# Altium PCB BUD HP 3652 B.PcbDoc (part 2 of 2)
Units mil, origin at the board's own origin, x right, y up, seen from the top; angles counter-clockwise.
Board outline 2604 x 4002 mil, 2 copper layers (Top Layer, Bottom Layer); 80 components, 93 nets, 415 pads, 235 vias.
Unrouted connection lines stored in the file: 48.
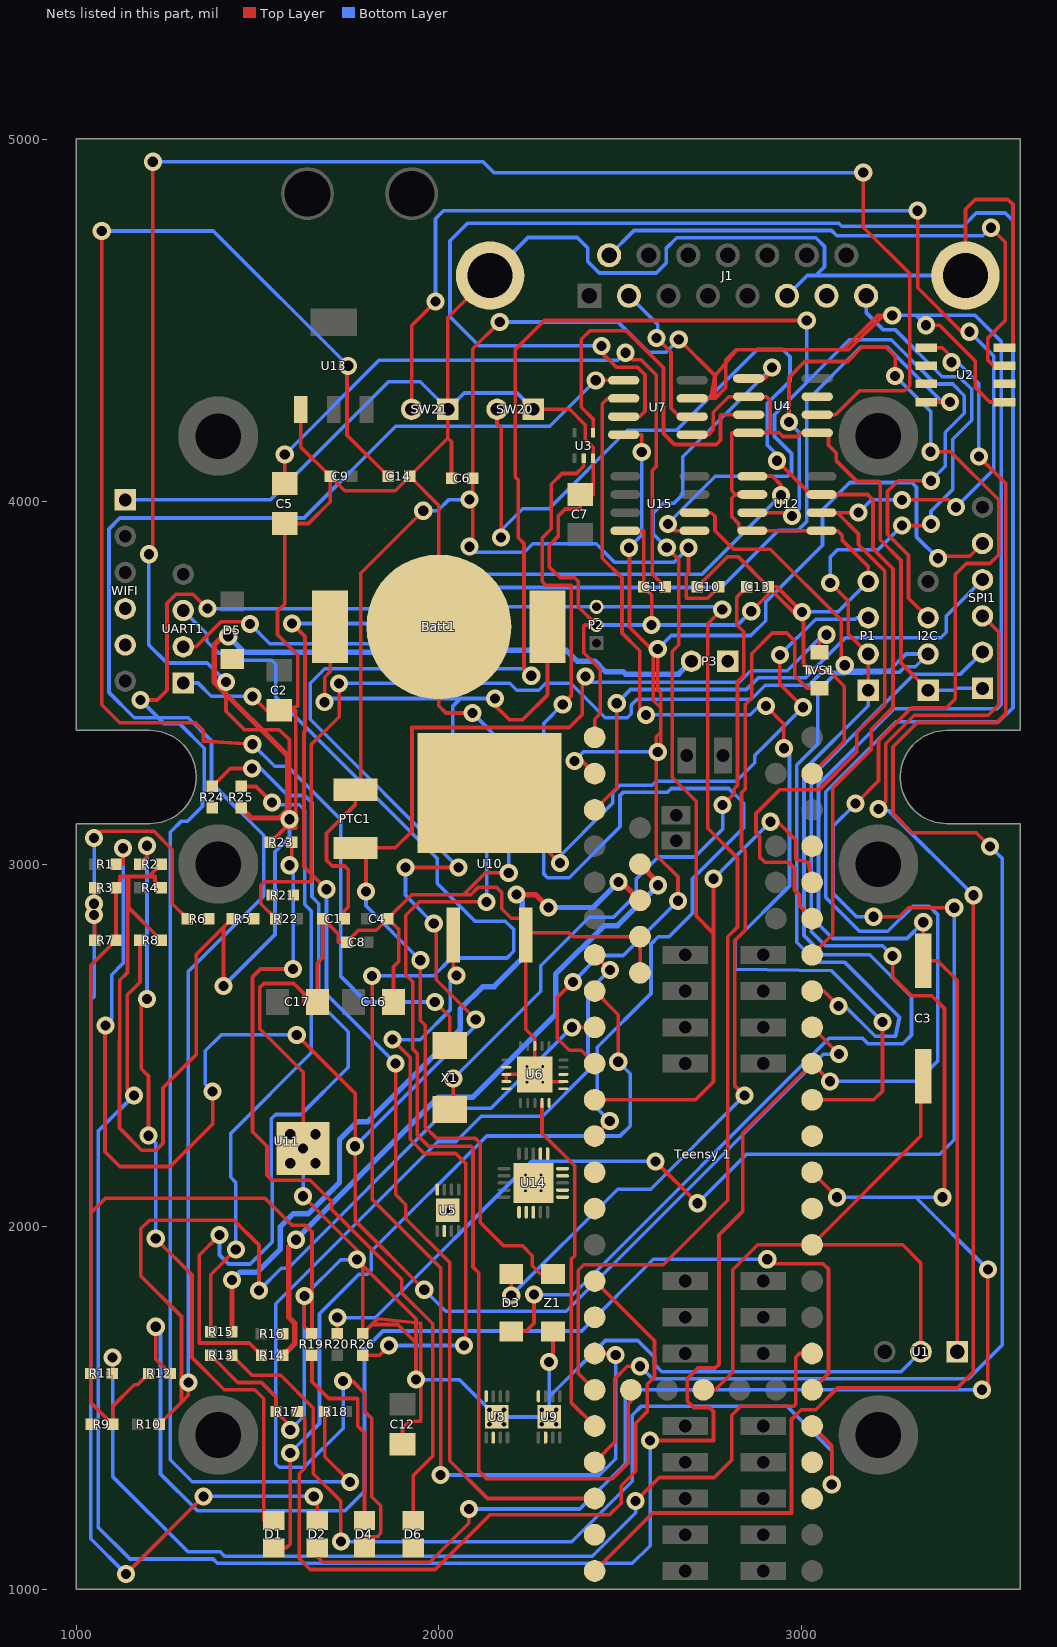
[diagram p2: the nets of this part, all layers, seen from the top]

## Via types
v1: diameter 50, hole 28, Top Layer to Bottom Layer, 215 vias
v2: diameter 20, hole 13, Top Layer to Bottom Layer, 12 vias
v3: diameter 19.68, hole 7.87, Top Layer to Bottom Layer, 8 vias

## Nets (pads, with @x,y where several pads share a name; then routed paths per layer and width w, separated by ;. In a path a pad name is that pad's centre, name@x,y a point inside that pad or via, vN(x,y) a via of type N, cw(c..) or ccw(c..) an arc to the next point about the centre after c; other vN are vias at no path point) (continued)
GND: "Teensy 1.14" "Teensy 1.17" "Teensy 1.32" "Teensy 1.78" "Teensy 1.79" "Teensy 1.90" Batt1.2 C1.1 C2.1 C3.2 C4.2 C5.1 C6.1 C7.2 C8.1 C9.1 C10.2 C11.1 C12.1 C13.1 C14.1 C16.1 C17.1 I2C.1 J1.6 J1.16 J1.17 P1.4 P2.2 R2.2 R3.2 R7.2 R8.2 R9.2 R11.2 R12.2 R13.2 R17.2 R19.2 R23.2 R26.2 SPI1.1 SW20.1 SW21.1 TVS1.3 U1.2 U2.8 U3.3 U4.2 U4.4 U4.5 U5.0 U5.2 U6.3 U6.4 U6.12 U6.18 U6.21 U7.5 U8.0 U8.2 U9.0 U9.2 U10.3 U11.29 U12.2 U12.4 U12.5 U13.1 U14.8 U14.21 U15.4 UART1.1 WIFI.1 Z1.1 | length 26122.3
  Top Layer w10: R12.2@1199.53,1595 1168.53,1564 1160,1564 1100,1504 R9.2@1100,1455 1040,1515 R11.2@1040,1595 1040,2037.9 ; R2.2@1234.05,3000 1200.05,2966 1144,2966 ; R8.2@1234.53,2790.06 1144,2880.59 1144,2966 ; R13.2@1370.47,1645 1445.47,1570 1510.95,1570 1550.95,1530 R17.2@1550.95,1490 1590,1450.95 v1(1590,1439) ; v1(1486,3463) 1524.12,3424.88 C2.1@1560,3424.88 ; R23.2@1535.47,3060 1575.51,3100.04 1605,3100.04 1605,3424.88 C2.1@1560,3424.88 ; U13.1@1619.45,4255 1619.45,4151.03 C9.1@1700.47,4070 ; v1(1625.71,2083.88) 1790,1919.58 v1@1790,1893 ; U11.29@1625.71,2215.91 1625.71,2426.29 1506,2546 1506,2660 1517,2671 1600,2671 1628,2643 1628,2620 C17.1@1665.12,2620 1665.12,2727 1680,2741.88 C1.1@1680,2850 1723,2807 1723,2785 C8.1@1745.47,2785 1778.47,2818 1827.53,2818 C4.2@1859.53,2850 ; v1(1629,1808.85) 1629,1725.53 R19.2@1650,1704.53 1650,1986 1632,2004 1595.08,2004 1521.18,2077.9 1080,2077.9 1040,2037.9 ; v1(1774,1909) v1@1790,1893 ; C16.1@1875,2620 1875,2717 1889,2731 1889,2820.53 C4.2@1859.53,2850 ; C12.1@1900,1399.88 1900,1443.62 1920,1463.62 1950.44,1463.62 1950.44,1733.35 1937,1734.82 ; v1(1937,1578) 1937,1680 ; C6.1@2035,4065 2035,4165.47 2025,4175.47 ; v1(2093,3417) 2020,3417 2000,3437 Batt1.2@2000,3655 2000,3989.53 C14.1@1919.53,4070 ; J1.16@2141.26,4624.09 2025,4507.83 SW21.1@2025,4255 2025,4175.47 ; U6.4@2186.26,2400.32 U6.3@2186.26,2420 U6.21@2265,2420 ; v1(2193,2976) 2128,2976 2068,2916 ; SW20.1@2260.71,4255 2361,4255 2404,4212 2404,4171.59 2425.59,4150 U3.3@2425.59,4119.57 2425.59,4020 C7.2@2390,4020 ; v1(2304.37,1626.37) 2315,1637 Z1.1@2315,1711 ; U6.12@2343.74,2400.32 2284.68,2400.32 U6.21@2265,2420 ; C7.2@2390,4020.12 C7.2@2390,4020 ; 2430,3350 2430,3400 2445,3415 2445,3538.33 2400,3583.33 2400,3657 2403,3660 P2.2@2435,3660 2385,3710 2385,3780 2375,3790 2335,3790 2305,3820 2305,3880.19 2330,3905.19 2330,3961 2349,3980 2390,3980 C7.2@2390,4020 ; U15.4@2514.53,3920 2565,3920 2565.47,3919.53 C11.1@2565.47,3765 2587,3743.47 v1(2587,3660) ; 2555,2700 2555.85,2700.85 2555.85,2765 2555,2765.85 2555,2800 2369.78,2800 2359.41,2810.37 U10.3@2240,2810.37 ; U7.5@2698.98,4185 2744,4185 2757.28,4198.28 2757.28,4247.28 2800,4290 U4.2@2855,4290 2904,4290 2914,4280 2914,4200 2904,4190 ; C10.2@2713.11,3765 2796.86,3848.75 2825.31,3848.75 C13.1@2909.05,3765 ; 2730,1550 2762.34,1550 2811,1598.66 2811,1881 2880,1950 3030,1950 ; v1(2862,3698) 2909.05,3745.05 C13.1@2909.05,3765 ; U12.2@2865,4020 2818,4020 ; v1(3002,3696) 2933,3765 C13.1@2909.05,3765 ; 3030,3250 3118.65,3338.65 3118.65,3491.35 TVS1.3@3075,3535 TVS1.3@3025,3535 3006,3554 3006,3668.05 C13.1@2909.05,3765 ; P1.4@3185,3780 3185,3821.58 3113.54,3893.04 3113.54,3906.46 3100,3920 U12.5@3055.94,3920 U12.4@2865,3920 2827.08,3920 2827.08,3940 2808,3959.08 2808,4010 2818,4020 ; U1.2@3330,1655 3330,1900 3280,1950 3030,1950 ; C3.2@3336.5,2415 3336.5,2344.93 3330,2344.93 3330,2250 3030,1950 ; I2C.1@3350,3480 3275,3555 3275,3837.74 3218,3894.74 3218,4051 3213,4056 3154,4056 3096,4114 3096,4135 3075,4156 3075,4190 U4.5@3043.98,4190 2999,4190 2989,4180 2949,4180 2939,4190 2904,4190 ; J1.17@3453.07,4624.09 3453.07,4807.07 3480,4834 3570,4834 3584,4820 3584,4425 U2.8@3560.75,4425 ; 1040,2037.9 1040,2720.54 R7.2@1109.53,2790.06 R3.2@1109.53,2935 1120.53,2946 1120.53,2966 1144,2966 ; C2.1@1560,3424.88 1611,3435.88 1611,3577 1555,3633 1555,3698 1575,3718 C5.1@1575,3939.88 1640.36,3939.88 1700.47,4000 C9.1@1700.47,4070 ; C9.1@1700.47,4070 1740.48,4030 1879.52,4030 C14.1@1919.53,4070 ; v1@1790,1893 1937,1746 1937,1734.82 ; v1@1790,1893 R26.2@1790,1704.53 1815.47,1730 ; 1815.47,1730 1831.84,1746.37 1937,1734.82 ; 1815.47,1730 1887,1730 1937,1680 ; C4.2@1859.53,2850 1925.53,2916 2068,2916 ; C14.1@1919.53,4070 2025,4175.47 ; 1937,1680 1937,1734.82 ; 2068,2916 2088,2916 2108,2936 2160,2936 2174,2922 2174,2877 2200,2851 2240,2851 U10.3@2240,2810.37 ; U10.3@2240,2810.37 U10.3@2240,2804.84 2240,2545 2265,2520 U6.18@2265,2498.74 U6.21@2265,2420 ; 2818,4020 2808,4030 2808,4190 U4.4@2855,4190 2904,4190
  Bottom Layer w10: WIFI.1@1135,4005 1535,4005 1861.09,4331.09 1948.91,4331.09 SW21.1@2025,4255 2070,4300 2215.71,4300 SW20.1@2260.71,4255 ; UART1.1@1295,3500 1335.51,3500 1372.51,3463 v1(1486,3463) ; v1(1590,1439) 1629,1478 v1(1629,1808.85) 1729.15,1909 v1(1774,1909) ; v1(1625.71,2083.88) U11.29@1625.71,2215.91 ; v1(1937,1578) 2057,1578 v2(2140,1495) U8.0@2160,1475 U9.0@2304.37,1475 2304.37,1530.37 ; v1(2093,3417) 2193,3317 v1(2193,2976) ; J1.16@2141.26,4624.09 2246.17,4729 2382,4729 2411,4700 2411,4663 2443,4631 2600,4631 2628,4659 2628,4700 2656.27,4728.27 3040,4728.27 3064,4704.27 3064,4648 3040.09,4624.09 ; v1(2304.37,1626.37) 2304.37,1530.37 ; P2.2@2435,3660 v1(2587,3660) 2824,3660 v1(2862,3698) ; J1.6@2960.75,4568.19 3016.56,4624 ; v1(3002,3696) 3101,3696 P1.4@3185,3780 ; U1.2@3330,1655 3275,1600 2615,1600 2595,1620 2595,1640 2549,1686 2460,1686 2304.37,1530.37 ; I2C.1@3350,3480 3422,3480 3427,3485 SPI1.1@3500,3485 ; J1.17@3453.07,4624.09 3040.09,4624.09 ; 3016.56,4624 3016.65,4624.09 3040.09,4624.09 ; 3016.56,4624 3040,4624 3040.09,4624.09
  other v2: 2140,1455 2180,1455 2284.37,1455 2324.37,1455 2180,1495 2284.37,1495 2324.37,1495
  other v3: 2239.05,2098.98 2282.36,2098.98 2239.05,2142.28 2282.36,2142.28 2243.35,2398.35 2286.65,2398.35 2243.35,2441.65 2286.65,2441.65
"GPS RX": "Teensy 1.41" P2.3 UART1.2 | length 4118.3
  Top Layer w10: UART1.2@1295,3600 1330.2,3600 1399.2,3669 1473,3669 v1(1479,3663) ; 2430,1550 2385,1595 2385,1880 2400,1895 2619,1895 2797,2073 2797,2800 2824,2827 2824,3017 2742,3099 2742,3663 v1(2782,3703)
  Bottom Layer w10: v1(1479,3663) 1534,3608 2053,3608 2155,3710 P2.3@2435,3710 2775,3710 v1(2782,3703)
"GPS TX": "Teensy 1.40" UART1.3 | length 4162
  Top Layer w10: v1(1816,2692) 1816,2075 2005,1886 v1(2005,1315) ; 2430,1650 2484,1650 v1(2488,1646)
  Bottom Layer w10: UART1.3@1295,3700 1359.53,3635.47 1359.53,3615.47 1393.51,3581.49 1413.68,3581.49 1432.67,3562.5 1538.79,3562.5 1550.14,3551.14 1550.14,3461.56 1996,3015.71 1996,2947 2100,2843 2183.53,2843 2206.53,2820 2206.53,2759.53 2188.06,2741.06 2035.06,2741.06 1986,2692 v1(1816,2692) ; v1(2005,1315) 2443,1315 2488,1360 v1(2488,1646)
"Hst USB_N": "Teensy 1.76" R14.1 | length 1895.3
  Top Layer w15: R14.1@1570,1645 1603,1678 1603,1733.5 1586.5,1750 1586.5,1944.5 v1(1606,1964) ; 2555,3000 2605,2950 v1(2605,2941.82)
  Bottom Layer w15: v1(1606,1964) 1999.49,2357.49 2094.07,2357.49 2322.5,2585.92 2322.5,2696.5 2456.48,2830.48 2493.66,2830.48 v1(2605,2941.82)
"Hst USB_P": "Teensy 1.77" R15.1 | length 2037.6
  Top Layer w15: R15.1@1429.53,1710 v1(1429.53,1852.53) ; v1(2214,2916) 2267,2916 v1(2302.5,2880.5) ; v1(2496,2951) 2504,2951 2555,2900
  Bottom Layer w15: v1(1429.53,1852.53) 1451.5,1874.5 1499.5,1874.5 1563,1938 1563,2000 1599,2036 1640,2036 1726,2122 1726,2240 1775.47,2289.47 1804.65,2289.47 2059,2543.82 2059,2600 2121.5,2662.5 2152.5,2662.5 2230,2740 2230,2900 v1(2214,2916) ; v1(2302.5,2880.5) 2425.5,2880.5 v1(2496,2951)
"J1708 RX": "Teensy 1.4" "Teensy 1.29" U4.1 | length 3246.2
  Top Layer w10: 2430,2350 2708,2350 2758,2400 2758,2809 ; v1(2629,3874) 2662.36,3840.64 2662.36,3605.36 2644,3587 2644,3240 2710,3174 2710,2857 2758,2809 ; v1(2758,2960) 2758,2809 ; U4.1@2855,4340 2899,4340 2919,4360 v1(2919,4370) ; v1(2915,3117) 2935,3117 2985,3067 2985,3014 3020,3005 3030,2950
  Bottom Layer w10: v1(2629,3874) 2592,3911 2592,3968 2620,3996 2649,3996 2673,4020 2673,4124 v1(2919,4370) ; v1(2758,2960) v1(2915,3117)
"J1708 TX": "Teensy 1.3" U3.2 | length 3181.5
  Top Layer w10: v1(2342,3441) 2365,3464 2365,3770 2295,3770 2285,3780 2285,3900.19 2310,3925.19 2310,4048 2340,4078 2380,4078 2400,4098 U3.2@2400,4119.57 ; 2430,2250 v1(2471.5,2291.5)
  Bottom Layer w10: v1(2342,3441) 2290,3389 2290,2973 2300,2963 2360,2963 2500,3103 2500,3189.71 2508.29,3198 2630.63,3198 2641.63,3209 2800,3209 2841,3168 2841,3101 2700,2960 2700,2865 2635,2800 2605.49,2800 2585.49,2780 2585.49,2643.21 2437.28,2495 2437.28,2325.72 v1(2471.5,2291.5)
J1708+: R5.2 U6.5
J1708-: R6.2 U6.2
LIN: J1.2 U6.10 U7.6 | length 428.9
  Top Layer w10: v1(2600.67,4452.05) 2640.67,4412.05 2640.67,4258 2663.67,4235 U7.6@2698.98,4235
  Bottom Layer w10: J1.2@2524.53,4568.19 2603.98,4488.74 2603.98,4455.36 v1(2600.67,4452.05)
"LIN1 RX": "Teensy 1.6" R10.1 U7.1 | length 6683.4
  Top Layer w10: R10.1@1229.05,1455 1290,1515.95 ; v1(1309,1570) 1309,1534.95 1290,1515.95 ; v1(1504,1824) 1504,1949.22 1436,2017.22 1201.22,2017.22 1178,1994 1178,1864 1290,1752 1290,1515.95 ; v1(2367.2,2550) 2430,2550 ; v1(2433,4335) U7.1@2510,4335
  Bottom Layer w10: v1(1309,1570) 1309,2704 1517,2912 1517,3080 1373,3224 1373,3340 1309,3404 1160,3404 1090,3474 1090,3925 1120,3955 1628,3955 1881,4208 2306,4208 v1(2433,4335) ; v1(1504,1824) 1565.5,1885.5 1584.5,1885.5 2026.17,2327.17 2144.37,2327.17 v1(2367.2,2550)
"LIN1 TX": "Teensy 1.5" U7.4 | length 2103.9
  Top Layer w10: v1(2370,2675) 2327,2632 2327,2520 2360,2487 2393,2487 2430,2450 ; U7.4@2510,4185 2560,4185 v1(2560,4137) ; v1(2525,3873) 2526,3872 2526,3654 2592,3588 2592,3452 2612,3432 2612,3364 2600,3352 2600,3025 2660,2965 v1(2660,2899)
  Bottom Layer w10: v1(2370,2675) 2443,2748 2509,2748 v1(2660,2899) ; v1(2525,3873) 2560,3908 v1(2560,4137)
"LIN !WAKE": "Teensy 1.24" R8.1 U7.3 | length 11016.5
  Top Layer w10: v1(1159,2362) 1140,2381 1140,2638.72 1175.47,2674.2 R8.1@1175.47,2790.06 ; v1(2449,4430) 2449,4412 2490,4371 2548,4371 2569,4350 2569,4250 2554,4235 U7.3@2510,4235 ; v1(2583,1410) 2758,1410 2758,1490 2748,1500 2705,1500 2685,1520 2685,1580 2715,1610 2763,1610 2773,1620 2773,1977 2839,2043 2839,2259 3030,2450 v1(3079,2401)
  Bottom Layer w10: v1(1159,2362) 1060,2263 1060,1171 1148.02,1082.98 1376.86,1082.98 1388.84,1071 2534,1071 2583,1120 v1(2583,1410) ; v1(2449,4430) 2111,4430 2031,4510 2031,4720 2079.27,4768.27 3103.54,4768.27 3111.81,4760 3446.59,4760 3483.11,4796.52 3563,4796.52 3584,4775.52 3584,3432 3545,3393 3260.5,3393 3067.5,3200 3067.5,2908.31 3160.81,2815 3239,2815 3308,2884 3353,2884 3377,2860 3377,2458 3320,2401 v1(3079,2401)
"LIN CS": "Teensy 1.23" R9.1 U7.2 | length 2989.2
  Top Layer w10: U7.2@2510,4285 2466,4285 2451,4270 2451,3844.39 2505.47,3789.91 2505.47,3637.93 2554.14,3589.27 2554.14,3429.86 v1(2572,3412) ; v1(2903,3436) 2952,3387 v1(2952,3320) ; 3030,2350 3200,2350 3224,2374 v1(3224,2565)
  Bottom Layer w10: v1(2572,3412) 2859,3412 2883,3436 v1(2903,3436) ; v1(2952,3320) 2967.5,3304.5 2967.5,2940 2817.5,2790 2817.5,2710 3082.5,2706.5 v1(3224,2565)
"LIN Switch": "Teensy 1.42" U6.9 | length 959.7
  Top Layer w10: U6.9@2284.68,2341.26 2284.68,2258 2375,2167.68 2375,1920 2365,1910 2365,1515 2430,1450
NetBatt1_1: "Teensy 1.15" Batt1.1 | length 4261.6
  Top Layer w10: v1(1685,3447) 1685,3516 1700,3531 Batt1.1@1700,3655 ; v1(2132,2896) 1946,2896 1909,2859 1909,2695 1928,2676 1928,2490 1941,2477 1941,2252.49 1971.49,2222 2089,2222 2094.45,2216.55 2094.45,1888.45 2110,1872.9 2110,1326 2131,1305 2480,1305 2523,1348 2523,1511 2530,1518 2530,1550 ; v1(2155,3457) 2155,3438 2194,3399 2232,3399 2300,3467 Batt1.1@2300,3655
  Bottom Layer w10: v1(1685,3447) 1695,3457 2060,3457 ; v1(2132,2896) 2132,3077 2038,3171 2038,3435 2060,3457 ; v1(2155,3457) 2060,3457
NetC5_2: C5.2 C11.2 | length 1850.7
  Top Layer w10: C5.2@1575,4050.12 v1(1575,4130) ; v1(2515,4411) 2533.95,4392.05 2557.76,4392.05 2600,4349.81 2600,4097 2589,4086 2589,3800.53 C11.2@2624.53,3765
  Bottom Layer w10: v1(1575,4130) 1835,4390 2494,4390 v1(2515,4411)
NetC13_2: C13.2 U14.7 X1.1 | length 1902.5
  Top Layer w10: X1.1@2030,2322.83 2040,2322.83 v1(2040,2408.26) ; v1(2783,3163) 2815,3195 2815,3208 2824,3217 2824,3503 2841.69,3520.69 2841.69,3641.31 2822,3661 2822,3737 C13.2@2850,3765
  Bottom Layer w10: v1(2040,2408.26) 2281,2649.26 2281,2720 2414.83,2853.83 2482.12,2853.83 2545.25,2916.96 2545.25,2960 2605.25,3020 2706.16,3020 2783,3096.84 v1(2783,3163)
NetC14_2: C14.2 U14.6 X1.2 | length 4157.1
  Top Layer w10: v1(1070,4747) 1070,3440 1120,3390 1329,3390 1350,3369 1350,3340 v1(1486,3331) ; v1(1750,4375) 1746.85,4371.85 1746.85,4183.62 C14.2@1860.47,4070 ; v1(1989,2620) 2030,2579 X1.2@2030,2500
  Bottom Layer w10: v1(1070,4747) 1378,4747 v1(1750,4375) ; v1(1486,3331) 1547,3270 1582.7,3270 1730,3122.7 1730,2690 1800,2620 v1(1989,2620)
NetD1_1: "Teensy 1.7" D1.1 | length 2232.7
  Top Layer w10: D1.1@1545,1114.6 1580,1114.6 1590,1124.6 v1(1590,1376) ; 2430,2650 2495,2585 v1(2495,2455)
  Bottom Layer w10: v1(1590,1376) 1671,1457 1671,1760 1780,1869 1803,1869 1814,1880 1814,1932 2132,2250 2500,2250 2528,2278 2528,2422 v1(2495,2455)
NetD1_2: D1.2 R2.1 | length 2144.7
  Top Layer w10: R2.1@1175,3000 1195,3020 v1(1195,3051) ; v1(1195,2628) 1179,2612 1179,2435.84 1199,2415.84 v1(1199,2251) ; v1(1219,1967) 1319,1867 1319,1639 1408,1550 1492,1550 1517,1525 1517,1189.4 D1.2@1545,1189.4
  Bottom Layer w10: v1(1195,2628) v1(1195,3051) ; v1(1199,2251) 1219,2231 v1(1219,1967)
NetD2_1: "Teensy 1.21" D2.1 SPI1.2 | length 5256.9
  Top Layer w10: D2.1@1665,1114.6 1665,1089 1680,1074 1975,1074 2083,1182 v1(2083,1221) ; 3030,2150 v1(3099,2081) ; v1(3252,2747) 3252,2689 3304,2637 3360,2637 3395,2602 3395,2086 v1(3390,2081) ; v1(3499,1550) 3515,1566 v1(3515,1882)
  Bottom Layer w10: v1(2083,1221) 2389,1221 2514,1346 2514,1532 2532,1550 v1(3499,1550) ; v1(3099,2081) 3316,2081 ; v1(3252,2747) 3224,2775 3066.91,2775 3027.5,2814.41 3027.5,3240 3312.03,3524.53 3439.53,3524.53 SPI1.2@3500,3585 ; v1(3390,2081) 3316,2081 ; v1(3515,1882) 3316,2081
NetD2_2: D2.2 R3.1 | length 2615.8
  Top Layer w10: v1(1049,2891) 1049,2935 R3.1@1050.47,2935 ; v1(1137,1042) v1(1351,1256) ; v1(1655,1256) 1665,1246 D2.2@1665,1189.4
  Bottom Layer w10: v1(1049,2891) 1049,2635 1040,2626 1040,1139 v1(1137,1042) ; v1(1351,1256) v1(1655,1256)
NetD3_2: D3.2 TVS1.1 | length 2519
  Top Layer w10: v1(2200,1810) D3.2@2200,1870 ; v1(2843,2362) 2817,2388 2817,2790 2845,2818 2845,3037 2835,3047 2835,3197 2845,3207 2845,3440 2863,3458 2863,3581 2920,3638 2960,3638 2982,3616 2982,3520 3017,3485 TVS1.1@3050,3485
  Bottom Layer w10: v1(2200,1810) 2493.57,2103.57 2584.57,2103.57 v1(2843,2362)
NetD4_1: "Teensy 1.8" D4.1 | length 2853.4
  Top Layer w10: v1(1736,1574) 1762,1574 1796,1540 1796,1490 1815,1471 1815,1255 1840,1230 1840,1154 1830,1144 1795,1144 D4.1@1795,1114.6 ; 2430,2750 v1(2472,2708)
  Bottom Layer w10: v1(1736,1574) 1736,1444 1628,1336 1560,1336 1550,1346 1550,1787.49 1997.13,2234.62 2046.43,2234.62 2116.79,2304.97 2286.57,2304.97 2411.67,2430.07 2411.67,2647.67 v1(2472,2708)
NetD4_2: D4.2 R19.1 | length 562.4
  Top Layer w10: R19.1@1650,1645.47 1650,1571.96 1696,1525.96 1775.04,1525.96 1776,1525 1776,1450.12 1795,1431.12 D4.2@1795,1189.4
NetD5_1: D5.1
NetD6_1: D6.1
NetD6_2: D6.2 R23.1 | length 2266.1
  Top Layer w10: v1(1588,2997) 1594.53,3003.53 R23.1@1594.53,3060 ; v1(1598,2711) 1508,2711 1486,2689 1486,2261.85 1526,2221.85 1526,2142 1540,2128 1645.41,2128 1704.62,2068.79 1704.62,2047.29 1897.36,1854.55 1897.36,1817.47 1983,1731.83 1983,1367.13 1930,1314.13 D6.2@1930,1189.4
  Bottom Layer w10: v1(1588,2997) 1598,2987 v1(1598,2711)
NetI2C_2: "Teensy 1.26" I2C.2 R22.2 U15.6 | length 5198.5
  Top Layer w10: R22.2@1550,2850 1509,2891 1509,2941 1520,2952 1648,2952 1648,3330 1725,3407 v1(1725,3499) ; U15.6@2705.47,3970 2752,3970 2762,3960 2762,3920 2813.25,3868.75 2914.74,3868.75 3110,3673.48 3110,3559 v1(3120,3549) ; 3030,2650 3062,2650 v1(3103,2609)
  Bottom Layer w10: v1(1725,3499) 2196,3499 2215,3480 2276,3480 2295,3499 2364,3499 2459,3404 2520,3404 2531,3415 2531,3439 2547.01,3455.01 2862.01,3455.01 2901,3494 3021,3494 3057,3530 3270.94,3530 ; v1(3103,2609) 3120,2609 3204,2525 3260,2525 3271,2578 3119,2730 3041.89,2730 2987.5,2784.39 2987.5,3273.5 3045,3331 3045,3477 3093,3525 3120.65,3525.78 3270.94,3530 ; v1(3120,3549) 3134,3535 3244,3535 3289,3580 I2C.2@3350,3580 3314.53,3544.53 3285.47,3544.53 3270.94,3530
NetI2C_3: "Teensy 1.25" I2C.3 R1.2 U15.5 | length 11144.4
  Top Layer w10: v1(1080,2555) 1079,2554 1079,2207 1120,2166 1259,2166 1376,2283 v1(1376,2373) ; R1.2@1109.53,3000 1129,3000 v1(1129,3044) ; v1(1608,2529) 1769,2368 v1(1769,2222) 1769,2017 v1(1960,1826) ; v1(1908,2991) v1(2054,2991) ; v1(1986,2836) 1993,2829 1993,2681 v1(2102,2572) ; v1(2255,3520) 2235,3540 2235,3885 2219,3901 2219,4060 2211,4068 2211,4420 2291,4500 v1(3015,4500) ; v1(2632,3939) 2651,3920 U15.5@2705.47,3920 ; 3030,2550 v1(3104,2476) ; I2C.3@3350,3680 3296,3734 3296,3851.97 3238,3909.97 3238,4028.76 3267.24,4058 v1(3357.5,4058)
  Bottom Layer w10: v1(1080,2555) 1097.5,2572.5 1097.5,2694.97 1129,2726.47 v1(1129,3044) ; v1(1376,2373) 1356,2393 1356,2485 1400,2529 v1(1608,2529) ; v1(1769,2222) 2102,2555 v1(2102,2572) ; v1(1908,2991) 1908,2914 v1(1986,2836) ; v1(1960,1826) 2018.99,1767.01 ; v1(2054,2991) 1645,3400 1645,3499 1685,3539 2236,3539 v1(2255,3520) ; v1(2632,3939) 2763,4070 2963,4070 2973,4080 2973,4133 2926,4180 2926,4240 ; v1(3015,4500) 3015,4329.33 ; v1(3104,2476) 3061,2476 2352.01,1767.01 ; v1(3357.5,4058) 3397.5,4098 3397.5,4191.95 3450,4244.45 3450,4292.64 3417.64,4325 3370.43,4325 3248.43,4447 3132.67,4447 3015,4329.33 ; 2019,1767 2352,1767 ; 2018.99,1767.01 2352.01,1767.01 ; 2926,4240 3015,4329 3015,4329.33 ; 2926,4240 2925.67,4240 3015,4329.33
NetP1_3: P1.3 U10.2 | length 1743.2
  Top Layer w10: U10.2@2140,3196.57 2140,3036 2301,3036 v1(2334,3003) ; v1(2941,3577) 2941,3497 v1(3005,3433)
  Bottom Layer w10: v1(2334,3003) 2314,3003 2480,3169 2480,3198 2500,3218 2589,3218 2600,3229 2821,3229 2872,3280 2872,3300 v1(3005,3433) ; v1(2941,3577) 3040,3676 3149,3676 3153,3680 P1.3@3185,3680
NetPTC1_1: PTC1.1 TVS1.2 Z1.2 | length 3339.6
  Top Layer w10: PTC1.1@1770,3045 PTC1.1@1799,3045 ; v1(1799,2925) PTC1.1@1799,3045 ; v1(1949,2735) 1949,2569.66 1962.83,2555.84 1962.83,2274.17 1992.63,2244.37 2100.08,2244.37 2114.45,2230 2114.45,2011.55 2178.74,1947.26 2230.74,1947.26 2258,1920 2258,1892 2280,1870 Z1.2@2315,1870 ; v1(2405,3518) 2396,3509 2396,3413 2360,3377 1926,3377 1926,3091 1880,3045 PTC1.1@1799,3045 ; TVS1.2@3050,3585 3050,3613 v1(3070,3633)
  Bottom Layer w10: v1(1799,2925) 1799,2885 v1(1949,2735) ; v1(2405,3518) 2421.11,3501.89 2828.89,3501.89 2861,3534 2961,3534 3060,3633 v1(3070,3633)
NetR4_2: R4.2 R5.1 U4.6 | length 7369
  Top Layer w10: v1(1200,3855) 1211,3866 v1(1211,4938) ; R4.2@1234.05,2935 1217,2952.05 1217,2966 1141,2966 1141,2701 1120,2680 1120,2515 1119,2514 1119,2272 1180,2211 1220,2211 1239,2230 1239,2383 1331,2475 1331,2751 1406,2826 ; v1(1406,2664) 1406,2826 ; v1(1413,3503) 1413,3422 1464,3371 1560,3371 1588,3343 v1(1588,3124) ; R5.1@1430,2850 1406,2826 ; U4.6@3043.98,4240 3094.22,4240 3160.72,4306.5 3285.5,4306.5 3299,4320 3299,4629.66 3171,4757.66 v1(3171,4908)
  Bottom Layer w10: v1(1200,3855) 1200,3605 1250,3555 1361,3555 v1(1413,3503) ; v1(1211,4938) 2122,4938 2152,4908 v1(3171,4908) ; v1(1406,2664) 1548,2806 1548,3034 1588,3074 v1(1588,3124)
NetR6_1: R6.1 R7.1 U4.7 | length 734.5
  Top Layer w10: v1(1049,2860) 1050.47,2858.53 R7.1@1050.47,2790.06 ; v1(1049,3072) 1068,3091 1214,3091 1265,3040 1265,2890.95 R6.1@1305.95,2850
  Bottom Layer w10: v1(1049,2860) v1(1049,3072)
NetR11_1: "Teensy 1.51" R11.1 U5.8 | length 2792.6
  Top Layer w10: R11.1@1099.05,1595 1100,1595.95 v1(1100,1639) ; v1(2543,1243) 2608,1308 2760,1308 2808,1356 2808,1480 2833,1505 2980,1505 2985,1510 2985,1640 2995,1650 3030,1650
  Bottom Layer w10: v1(1100,1639) 1100,1311 1308.02,1102.98 1396.86,1102.98 1408.84,1091 2423,1091 2543,1211 v1(2543,1243)
NetR12_1: "Teensy 1.50" R12.1 U8.8 | length 3321.6
  Top Layer w10: v1(1219,1724) 1219,1634.58 R12.1@1258.58,1595 ; v1(2906,1910) 2918,1898 3060,1898 3075,1883 3075,1595 3030,1550
  Bottom Layer w10: v1(1219,1724) 1232.21,1710.79 1232.21,1317.79 1334,1216 1741,1216 1795,1270 1795,1661.37 1845.86,1712.23 2394.24,1712.23 2592.01,1910 v1(2906,1910)
NetR13_1: "Teensy 1.49" R13.1 U9.8 | length 2627.3
  Top Layer w10: R13.1@1429.53,1645 1484.53,1590 1564,1590 1654,1500 1654,1318.32 1730,1242.32 v1(1730,1131) ; 3030,1450 3084,1396 v1(3084,1289)
  Bottom Layer w10: v1(1730,1131) 2367,1131 2534,1298 2534,1480 2559,1505 2960,1505 3084,1381 v1(3084,1289)
NetR14_2: R14.2 R24.2 | length 2460.4
  Top Layer w10: R24.2@1375,3214.53 1424.47,3264 v1(1485,3264) ; v1(1395,1977) 1339,1921 1339,1679 1476.95,1679 R14.2@1510.95,1645
  Bottom Layer w10: v1(1395,1977) 1395,1922 1420,1897 1480,1897 1540,1957 1540,2128 1537.87,2130.13 1537.87,2297.46 1550,2309.59 1619.59,2309.59 1750,2440 1750,2538 1669,2619 1669,2891 1650,2910 1650,3169.35 1629.71,3189.64 1583.15,3189.64 1508.79,3264 v1(1485,3264)
NetR15_2: R15.2 R25.2 | length 1775.5
  Top Layer w10: R15.2@1370.47,1710 1370.47,1867.47 v1(1440,1937) ; R25.2@1455,3214.53 1495.47,3214.53 v1(1540,3170)
  Bottom Layer w10: v1(1440,1937) 1440,2121.85 1425.65,2136.2 1425.65,2257.1 1648,2479.45 1648,2871 1630,2889 1630,3149.03 1614.7,3164.33 1545.67,3164.33 v1(1540,3170)
NetR16_1: R16.1
NetR17_1: "Teensy 1.38" R17.1 | length 2116.5
  Top Layer w10: R17.1@1610,1490 1630,1470 1630,1333.73 1614.59,1318.32 1614.59,1084.41 1645,1054 1990,1054 2141,1205 2471,1205 2503,1237 2503,1285 2543,1325 2543,1458 2575,1490 2575,1565 2595,1585 2595,1685 2430,1850
NetR18_2: R18.2 U12.1 | length 5278.7
  Top Layer w10: v1(1177,3453) 1223,3453 1250,3480 1250,3720 1275,3745 1322,3745 v1(1362,3705) ; R18.2@1685.47,1490 1685.47,1365.53 v1(1755,1296) ; U12.1@2865,4070 2920,4070 2944,4046 v1(2944,4018)
  Bottom Layer w10: v1(1177,3453) 1243,3387 1286,3387 1353,3320 1353,3177 1348,3172 1348,3160 1307,3119 1290,3119 1259,3088 1259,1357 1320,1296 v1(1755,1296) ; v1(1362,3705) 1938.81,3705 2034,3800.19 2726.19,3800.19 v1(2944,4018)
NetR20_2: R20.2 U12.3 | length 5824.5
  Top Layer w10: R20.2@1720,1704.53 v1(1720,1749) ; v1(2598,2180) v1(2713.5,2064.5) ; U12.3@2865,3970 2965,3970 v1(2974,3961) ; v1(2966,4220) 2966,4343 3010,4387 3128,4387 3167,4426 3233,4426 3259,4400 v1(3259,4347) ; v1(3150,3167) 3213,3230 3213,3340.57 3303.43,3431 3400,3431 3425,3456 3425,3799.53 3455,3829.53 3520,3829.53 3544.53,3854.06 3544.53,4005.47 3412,4138 v1(3357,4138) ; v1(3199,2855) 3270,2855 3295,2880 v1(3422,2880)
  Bottom Layer w10: v1(1720,1749) 1825,1749 2256,2180 v1(2598,2180) ; v1(2713.5,2064.5) 2849,2200 3382,2200 3422,2240 v1(3422,2880) ; v1(2966,4220) 2994,4192 2994,3981 v1(2974,3961) ; v1(3150,3167) 3087.5,3104.5 3087.5,2920 3152.5,2855 v1(3199,2855) ; v1(3259,4347) 3357,4249 v1(3357,4138)
NetR21_1: R21.1 U2.6
NetR26_1: R26.1 U10.1 | length 1682.6
  Top Layer w10: R26.1@1790,1645.47 1836.47,1645.47 v1(1863,1672) ; v1(1872,2516) 1921,2467 1921,2241 1960,2202 2047,2202 2074.45,2174.55 2074.45,1676.45 v1(2070,1672) ; U10.1@2040,2804.84 2040,2702 v1(2049,2693)
  Bottom Layer w10: v1(1863,1672) v1(2070,1672) ; v1(1872,2516) 1949,2516 2032,2599 2032,2676 v1(2049,2693)
NetSPI1_3: "Teensy 1.46" SPI1.3 | length 3906.9
  Top Layer w10: 2430,1050 2590,1210 2973,1210 2973,1468 3000,1495 3040,1495 3100,1555 3430,1555 3475,1600 v1(3475,2914.28) ; v1(3213,3152) 3233,3172 3233,3332.29 3311.71,3411 3515.53,3411 3544.53,3440 3544.53,3640.47 SPI1.3@3500,3685
  Bottom Layer w10: v1(3213,3152) 3218,3147 3242.28,3147 v1(3475,2914.28)
NetSPI1_4: "Teensy 1.12" SPI1.4 | length 1495.9
  Top Layer w10: 2430,3150 2491,3211 v1(2491,3444)
  Bottom Layer w10: v1(2491,3444) 2528.89,3481.89 2848.89,3481.89 2881,3514 3011,3514 3122,3625 3385,3625 3400,3640 3400,3685 SPI1.4@3500,3785
NetSPI1_5: "Teensy 1.13" SPI1.5 | length 1958.7
  Top Layer w10: v1(2374,3285) 2395,3285 2430,3250 ; v1(2604,3310) 2612,3318 2612,3474 2604,3482 v1(2604,3594) ; v1(3377,3844) 3382.53,3849.53 3464.53,3849.53 SPI1.5@3500,3885
  Bottom Layer w10: v1(2374,3285) 2399,3310 v1(2604,3310) ; v1(2604,3594) 2641,3631 2861,3631 2902,3672 2902,3723.41 3058.59,3880 3058.59,3977.59 3134,4053 3305,4053 3318,4040 3318,3903 v1(3377,3844)
NetSW20_2: "Teensy 1.27" SW20.2 U12.7 | length 3395.1
  Top Layer w10: SW20.2@2160.71,4255 2160.71,4214.29 2172,4203 v1(2172,3901) ; v1(2933,4113) 3026,4020 U12.7@3055.94,4020 3183,4020 3198,4005 3198,3870.24 3253,3815.24 3253,3432.25 3193,3372.25 3193,3316 3087,3210 3087,2807 3030,2750
  Bottom Layer w10: v1(2172,3901) 2172,3921 2232,3981 2304,3981 2520,4197 2655.95,4197 2878.95,4420 2949,4420 2969,4400 2969,4333.33 2905.67,4270 2905.67,4157.33 2933,4130 v1(2933,4113)
NetSW21_2: "Teensy 1.28" SW21.2 U12.6 | length 4734.5
  Top Layer w10: SW21.2@1925,4255 1925,4486 v1(1991,4552) ; 3030,2850 2995,2885 2995,2915 2981.42,2928.58 2981.42,2988.58 2965,3005 2900,3005 2885,3020 2885,3077 2875,3087 2875,3140 2940,3205 3048.64,3205 3153,3309.36 3153,3362.49 3230,3439.49 3230,3809 3158,3881 3158,3911 3099,3970 ; U12.6@3055.94,3970 3099,3970 ; v1(3158,3970) 3099,3970 ; v1(3278,4005) 3407,4005 v1(3427,3985) ; v1(3321,4803) 3321,4590 3442,4469 v1(3464,4469)
  Bottom Layer w10: v1(1991,4552) 1991,4781 2013,4803 v1(3321,4803) ; v1(3158,3970) 3193,4005 v1(3278,4005) ; v1(3427,3985) 3531,4089 3531,4402 v1(3464,4469)
"NetTeensy 1_1": "Teensy 1.1" U14.15
"NetTeensy 1_2": "Teensy 1.2" U14.14
"NetTeensy 1_20": "Teensy 1.20" U14.12
"NetTeensy 1_22": "Teensy 1.22" U14.16
"NetTeensy 1_30": "Teensy 1.30"
"NetTeensy 1_39": "Teensy 1.39"
"NetTeensy 1_45": "Teensy 1.45"
"NetTeensy 1_62": "Teensy 1.62" U14.11
"NetTeensy 1_63": "Teensy 1.63"
  other v1: 1590,2175 1660,2175 1590,2255 1660,2255
NetU2_2: U2.2
NetU2_3: U2.3
NetU3_4: U3.4 U4.3 | length 1053.5
  Top Layer w10: U3.4@2425.59,4190.43 2425.59,4228.41 2393,4261 2393,4448 2417,4472 2517.81,4472 2620,4369.81 2620,4188 2650,4158 2765.28,4158 2777.28,4170 2777.28,4238.28 2779,4240 U4.3@2855,4240
NetU11_14: WIFI.5
NetU11_19: WIFI.4
NetU14_17: U14.17
RAW: D3.1 J1.8 P1.1 P1.2 | length 4293.4
  Top Layer w10: D3.1@2200,1711 2240,1711 2262.52,1733.52 v1(2262.52,1812.52) ; v1(3080,3776) 3130,3726 3130,3635 P1.2@3185,3580 P1.1@3185,3480 ; v1(3278,3934) 3353,3934 v1(3358,3939)
  Bottom Layer w10: v1(2262.52,1812.52) 2369.24,1812.52 3076.71,2520 3169,2520 3184,2505 3280,2505 3304,2529 3304,2635 3189,2750 3061,2750 3007.5,2803.5 3007.5,3260 3185,3437.5 P1.1@3185,3480 ; v1(3080,3776) 3080,3847.68 3100,3867.68 3211.68,3867.68 v1(3278,3934) ; J1.8@3178.86,4568.19 3178.86,4522.14 3227,4474 3260,4474 3389,4345 3435.15,4345 3470,4310.15 3470,4224.45 3418,4172.45 3418,4033.82 3358,3973.82 v1(3358,3939)
"Safe 12V": C1.2 C3.1 C6.2 C10.1 PTC1.2 U1.1 U2.5 U6.13 U7.7 | length 9024.5
  Top Layer w10: C1.2@1739.05,2850 1739.05,2871 1750,2881.95 1750,2985.14 1740,2995.14 1705.86,2995.14 1690,3011 1690,3085 1770,3165 PTC1.2@1770,3205 1785,3205 1785,3803 v1(1957,3975) ; v1(2085,3876) 2094.05,3885.05 v1@2094.05,4015.05 ; v1(2085,4006) v1@2094.05,4015.05 ; v1(2168.01,4496) 2094.05,4422.05 C6.2@2094.05,4065 v1@2094.05,4015.05 ; v1(2662,4448) 2762,4348 ; v1(2689,3873) 2689,3802.64 2682.36,3796 2682.36,3734 2741.16,3734 C10.1@2772.16,3765 ; U7.7@2698.98,4285 2750,4285 ; v1(3251,4514) v1@3226,4514 ; v1(3336.5,2840) C3.1@3336.5,2733.9 3376.1,2733.9 3430,2680 U1.1@3430,1655 ; v1(3344,4487) 3381.52,4487 3480,4388.52 3480,4315 3520,4275 U2.5@3560.75,4275 ; 2750,4285 2762,4285 2792,4315 2792,4384.1 ; 2750,4285 2762,4348 ; 2750,4285 2762,4297 2762,4348 ; 2762,4348 2792,4384.1 ; 2792,4384.1 2821,4419 ; 2792,4384.1 2792,4391 2820,4419 2821,4419 ; 2821,4419 3116,4419 ; 3116,4419 3131,4419 v1@3226,4514 ; 3116,4419 3211,4514 v1@3226,4514
  Bottom Layer w10: v1(1957,3975) 1997,3975 2028,4006 v1(2085,4006) ; v1(2085,3876) 2100,3861 2236,3861 2259,3884 2434,3884 2485,3833 2649,3833 v1(2689,3873) ; v1(2168.01,4496) 2494.67,4496 2578.67,4412 2626,4412 v1(2662,4448) ; v1(3251,4514) 3317,4514 ; v1(3336.5,2840) 3291.5,2795 3087.19,2795 3047.5,2834.69 3047.5,3220 3256.5,3429 3541,3429 3552,3440 3552,4442 3480,4514 3317,4514 ; v1(3344,4487) 3317,4514
SHLD/LIN: J1.7 U6.11
SWCAN: J1.9 R21.2 U2.7 | length 1550.7
  Top Layer w10: v1(3523,4756) 3563,4716 3563,4500 3515,4452 3515,4390 3530,4375 U2.7@3560.75,4375
  Bottom Layer w10: J1.9@2470,4680 2538.27,4748.27 3083.54,4748.27 3097.81,4734 3501,4734 v1(3523,4756)
SWCANRX: "Teensy 1.44" U2.4 | length 5388.7
  Top Layer w10: v1(1595,3664) 1631,3628 1631,3367 1628,3364 1628,2993 v1(1690,2931) ; v1(1881,2450) 1881,2088.77 1909.18,2060.59 1909.18,2021.82 2030,1901 2030,1354.33 2134.33,1250 2430,1250 ; U2.4@3345,4275 v1(3410,4275)
  Bottom Layer w10: v1(1595,3664) 1978,3664 2077.27,3763.27 2779.22,3763.27 2936.74,3920.79 2990.57,3920.79 3015,3945.22 3015,4278.06 3162.94,4426 3238.18,4426 3389.18,4275 v1(3410,4275) ; v1(1690,2931) 1690,2641 v1(1881,2450)
SWCANTX: "Teensy 1.43" U2.1 | length 4755.5
  Top Layer w10: 2430,1350 2485,1405 2485,1580 2520,1615 v1(2555,1615) ; U2.1@3345,4425 3389,4425 3414,4400 v1(3414,4385) ; v1(3490,4125) 3564.53,4050.47 3564.53,3415.53 3540,3391 3320,3391 3253,3324 3253,3140 3306,3087 3483,3087 v1(3521,3049)
  Bottom Layer w10: v1(2555,1615) 2590,1580 3461,1580 3555,1674 3555,3015 v1(3521,3049) ; v1(3414,4385) 3431.77,4385 3490,4326.77 v1(3490,4125)
"USB D_N": P3.1 R24.1
"USB D_P": P3.2 R25.1 | length 2076.6
  Top Layer w15: v1(1419,3629) 1404,3629 1380,3605 1380,3502 1582.5,3299.5 1582.5,3150 1560,3127.5 1482.97,3127.5 R25.1@1455,3155.47
  Bottom Layer w15: v1(1419,3629) 1463,3585 2140,3585 2145,3590 2352,3590 2381.5,3560.5 2430.5,3560.5 2460.03,3530.97 2509.48,3530.97 2516.05,3524.39 2661.56,3524.39 P3.2@2697.17,3560
pads on no net: "Teensy 1.16" "Teensy 1.18" "Teensy 1.19" "Teensy 1.31" "Teensy 1.35" "Teensy 1.36" "Teensy 1.37" "Teensy 1.52" "Teensy 1.53" "Teensy 1.54" "Teensy 1.55" "Teensy 1.56" "Teensy 1.57" "Teensy 1.58" "Teensy 1.59" "Teensy 1.60" "Teensy 1.61" "Teensy 1.64" "Teensy 1.65" "Teensy 1.66" "Teensy 1.67" "Teensy 1.68" "Teensy 1.69" "Teensy 1.70" "Teensy 1.71" "Teensy 1.72" "Teensy 1.73" "Teensy 1.74" "Teensy 1.80" "Teensy 1.81" "Teensy 1.82" "Teensy 1.83" "Teensy 1.84" "Teensy 1.85" "Teensy 1.86" "Teensy 1.87" "Teensy 1.88" "Teensy 1.91" U3.1 U6.14 U6.15 U6.16 U6.17 U7.8 U11.1 U11.2 U11.3 U11.4 U11.5 U11.6 U11.7 U11.8 U11.9 U11.10 U11.11 U11.12 U11.13 U11.14 U11.15 U11.16 U11.17 U11.18 U11.19 U11.20 U11.21 U11.22 U11.23 U11.24 U11.25 U11.26 U11.27 U11.28 U14.1 U14.2 U14.3 U14.4 U14.5 U14.9 U14.10 U14.13 U15.1 U15.2 U15.3 U15.7 USB1.0 USB1.1 USB1.2 USB1.3 USB1.4 USB1.5 WIFI.2 WIFI.3 WIFI.6
copper on no net:
  other v2: 2005,2025 2045,2025 2005,2065 2045,2065

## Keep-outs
Top Layer:
  lines w10: 3604,3369 3401.5,3369 ccw(c3401.5,3240.5) 3401.5,3112 3604,3112 3604,1000 1000,1000 1000,3112 1202.5,3112 ccw(c1202.5,3240.5) 1202.5,3369 1000,3369 1000,5002 3604,5002

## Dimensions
3212.5,3000 to 3212.5,1425 on Top Layer
3212.5,4181.5 to 3212.5,3000 on Top Layer
3212.5,1425 to 1000,1000 on Top Layer
1391.5,1425 to 1000,1000 on Top Layer
1391.5,1425 to 1000,1000 on Top Layer
1000,5002 to 1000,1000 on Top Layer
1000,5002 to 3604,5002 on Top Layer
